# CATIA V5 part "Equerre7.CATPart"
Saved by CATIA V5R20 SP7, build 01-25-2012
Part number: Equerre7
Bounding box of the stored display mesh (mm): x 0 to 10, y -52.999 to -4.033, z 105.004 to 142.162
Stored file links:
  J:\ACHTUNG2\Equerre7.CATPart
  J:\ACHTUNG2\cmilovidof.CATProduct
  J:\ACHTUNG2\Bielle5.CATPart
  J:\ACHTUNG\IAO non optimisé fini et qui marche à rendre\Equerre7.CATPart
  J:\ACHTUNG\IAO non optimisé fini et qui marche à rendre\Patin2.CATPart
  J:\ACHTUNG2\skl_Bielle4.CATPart
  J:\ACHTUNG2\Levier1.CATPart
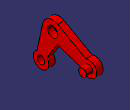
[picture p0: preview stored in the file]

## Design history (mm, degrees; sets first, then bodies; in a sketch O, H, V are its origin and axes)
External parameters (linked from other documents)
  External.diam_roue = 64 mm
  External.diam_roue.1 = 64 mm
Set1
  Plane1: linked copy from another document
  Line1 "Axe_Equerre7Patin3": linked copy from another document
  Line2 "Axe_Equerre7Socle": linked copy from another document
  Line3 "Axe_Equerre7Bielle5": linked copy from another document
  Line4 "Axe_Bielle5Equerre7": linked copy from another document
  Line5 to Line7: linked copy from another document
Body1 (main body)
  Sketch1 on Plane1, origin (5, 0, 0), H (0, 1, 0), V (0, 0, 1)
    arc A1 centre (-38.0408, 134.3395) radius 7.8611 from (-45.7242, 136.0012) to (-34.167, 141.1798) cw
    point P1 (-34.4484, 127.7558)
    point P2 (-34.4484, 127.7558)
    construction line L1 (-38.0408, 134.3395) -> (-34.4484, 127.7558)
    line L2 (-34.4484, 127.7558) -> (-15.5376, 121.2003)
    line L3 (-12.4866, 129.064) -> (-34.167, 141.1798)
    line L4 (-42.4628, 114.926) -> (-34.4484, 127.7558)
    line L5 (-50.0086, 116.1912) -> (-45.7242, 136.0012)
    arc A2 centre (-10.0334, 123.5885) radius 6 from (-12.4866, 129.064) to (-15.5376, 121.2003) cw
    arc A3 centre (-47, 111) radius 6 from (-42.4628, 114.926) to (-50.0086, 116.1912) cw
    reference projected point E1 (-47, 111) from Line1
    circle A4 centre (-47, 111) radius 3
    circle A5 centre (-38.0408, 134.3395) radius 4
    reference projected point E2 (-10.0334, 123.5885) from Line5
    reference projected point E3 (-38.0408, 134.3395) from Line6
    reference projected point E4 (-38.0408, 134.3395) from Line6
    radius A1 = 7.8611
    radius A3 = 6 {= 6*External.diam_roue /64}
    radius A2 = 6 {= 6*External.diam_roue /64}
    radius A4 = 3 {= 3*External.diam_roue /64}
    radius A5 = 4 {= 4*External.diam_roue /64}
    length L1 = 7.5 {= 7.5*External.diam_roue.1 /64}
    coincidence: P2 P1
    concentricity: A3 E1, E2 A2, A5 E3, A1 E4
    tangency: L5 A1
  Pad1: profile Sketch1, direction (-1, 0, 0), length 5
  Sketch2 on start face of Pad1, origin (5, 0, 0), H (0, 1, 0), V (0, 0, 1)
    circle A1 centre (-10.0334, 123.5885) radius 3
    point P1 (-10.0334, 123.5885)
    reference projected point E1 (-10.0334, 123.5885) from Line5
    radius A1 = 3 {= 3*External.diam_roue /64}
    coincidence: P1 E1
  Pad2: profile Sketch2, direction (1, 0, 0), length 5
